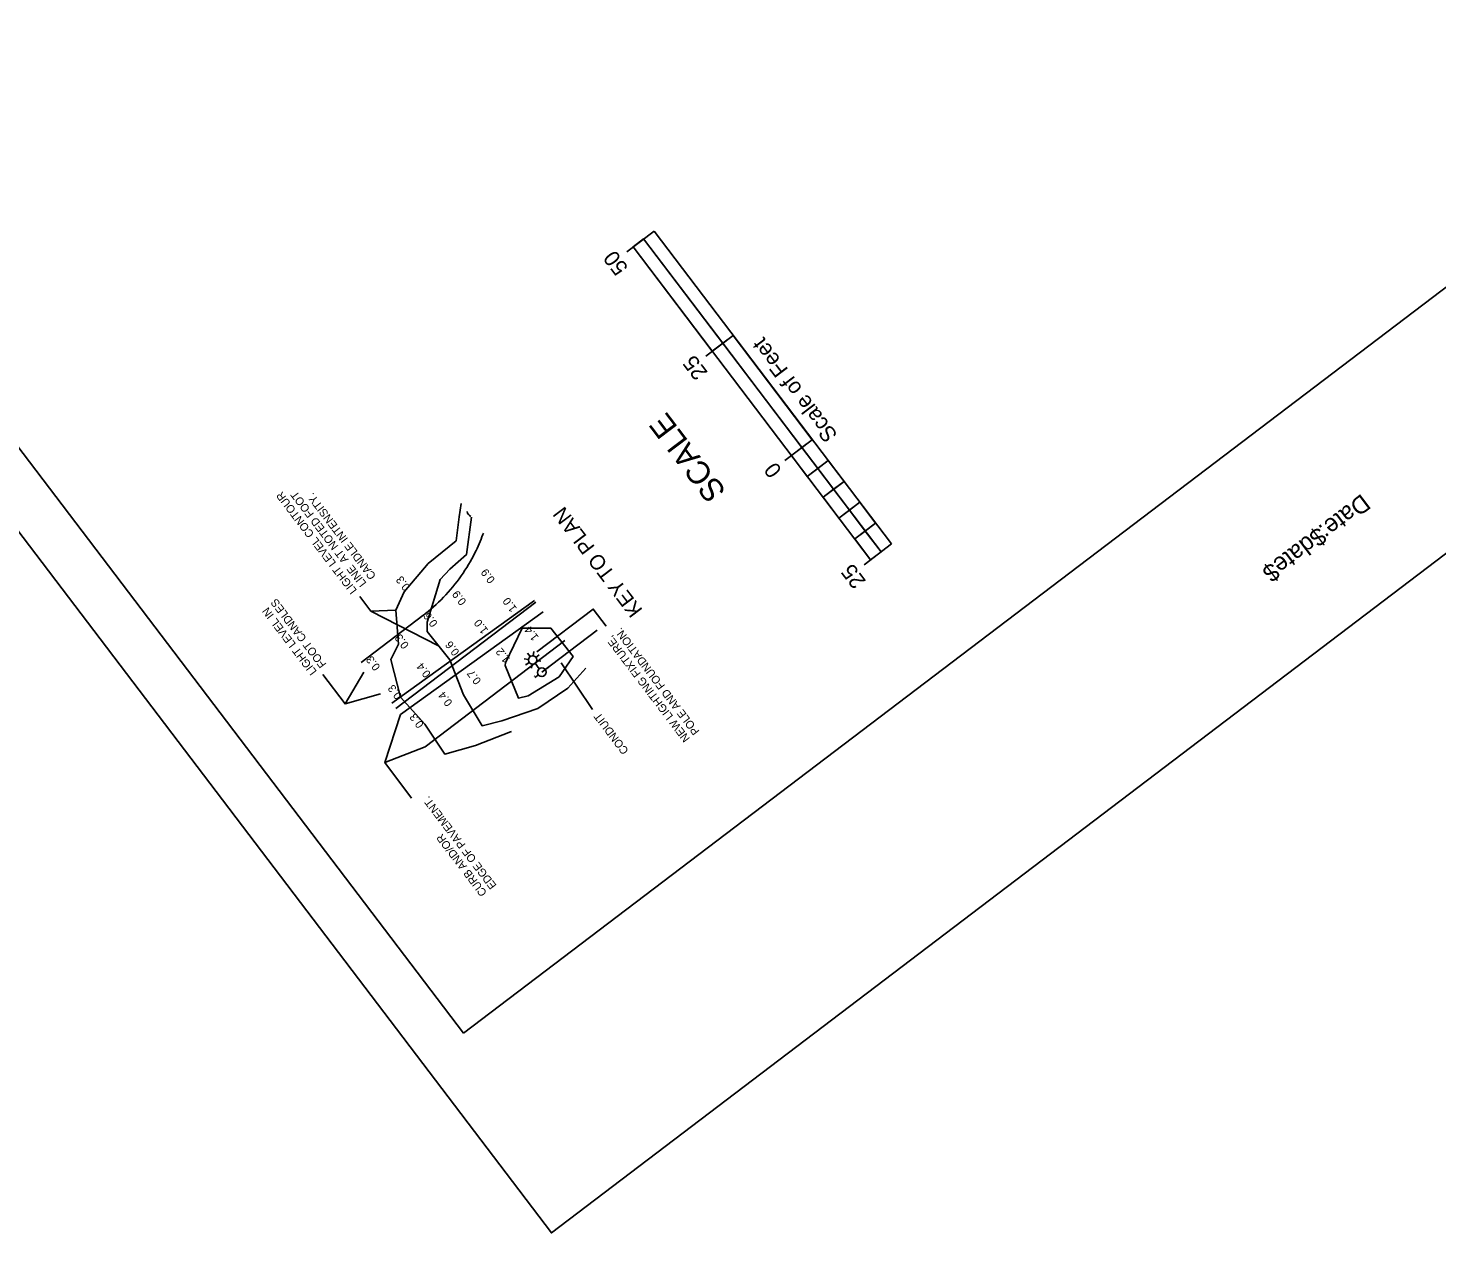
# Model space of a CAD drawing. Extents: x 1111477 to 1112429, y 616480 to 617490.
# Drawn here: x 1111891 to 1112159.9, y 616480.3 to 616710.3 of the extents above; entities that cross this region are included whole.
import ezdxf

# ---------------------------------------------------------------- set-up
doc = ezdxf.new("R2010")
doc.units = 0
for name, color, linetype in [('ANNOTATION', 7, 'Continuous'), ('D_Utilities_Pole_StreetLight', 7, 'Continuous'), ('H_V CONTROLS', 7, 'Continuous'), ('Liting Text', 7, 'Continuous'), ('VSL-LUMINAIRESCHEDULES', 7, 'Continuous'), ('VSL-STATISTICS', 7, 'Continuous')]:
    doc.layers.add(name, color=color, linetype=linetype)

msp = doc.modelspace()

# ---------------------------------------------------------------- linework, layer by layer
msp.add_lwpolyline([(1111990.86, 616480.3), (1111476.68, 617157.15), (1111914.64, 617489.85), (1112428.82, 616813)], close=True)
at = {"layer": 'ANNOTATION'}
for p, q in [((1111987.64, 616601.05), (1111960.41, 616581.46)), ((1111987.9, 616600.7), (1111961.2, 616580.42)), ((1111966.31, 616598.14), (1111954.55, 616589.2)), ((1111956.42, 616598.99), (1111969.32, 616592.41)), ((1111962.08, 616579.27), (1111989.31, 616598.85)), ((1111966.75, 616573.11), (1111993.45, 616593.39)), ((1111988.16, 616590.47), (1111988.13, 616590.5)), ((1111998.73, 616580.25), (1111992.75, 616589.16)), ((1111951.48, 616581.3), (1111955.05, 616587.36)), ((1111985.97, 616588.8), (1111985.94, 616588.84)), ((1111987.63, 616586.61), (1111987.6, 616586.65)), ((1111988.85, 616587), (1111988.85, 616587)), ((1111989.05, 616586.72), (1111989.05, 616586.72)), ((1111989.12, 616587.21), (1111989.12, 616587.21)), ((1111989.33, 616586.93), (1111989.33, 616586.93)), ((1111959.05, 616570.09), (1111966.75, 616573.11))]:
    msp.add_line(p, q, dxfattribs=at)
for points in [[(1111983.23, 616576.04), (1111983.05, 616575.95), (1111976.37, 616573.35), (1111970.51, 616571.7), (1111966.69, 616577.44), (1111962.05, 616582.57), (1111960.2, 616589.8), (1111961.7, 616592.71), (1111961.16, 616599.19), (1111962.78, 616602.68), (1111967.33, 616608.07), (1111972.66, 616612.43), (1111973.28, 616617.03), (1111973.62, 616619.54)], [(1111997.44, 616588.12), (1111993.98, 616584.3), (1111988.3, 616580.41), (1111981.43, 616578.08), (1111977.65, 616577.13), (1111974.06, 616583.04), (1111971.46, 616589.71), (1111967.18, 616595.11), (1111967.18, 616596.88), (1111969.61, 616605.07), (1111971.5, 616607.04), (1111974.65, 616609.81), (1111975.6, 616616.93)], [(1111954.3, 616601.79), (1111956.42, 616598.99), (1111961.16, 616599.19)], [(1112001.31, 616596.15), (1111998.85, 616599.39), (1111988.09, 616591.22)], [(1111995.03, 616590.33), (1111990.79, 616595.75), (1111985.29, 616595.78), (1111982.1, 616589.15), (1111982.07, 616588.63), (1111984.58, 616582.39), (1111986.45, 616582.86), (1111992.34, 616586.48), (1111995.03, 616590.33)], [(1111947.23, 616586.9), (1111951.48, 616581.3), (1111958.24, 616583.23)], [(1111964.19, 616563.31), (1111959.05, 616570.09), (1111962.08, 616579.27)]]:
    msp.add_lwpolyline(points, dxfattribs=at)
for centre, major_axis, start_param, end_param in [((1111976.12, 616618.3), (-0.05, 1.38), 1.737973, 2.633498), ((1111945.51, 616625.57), (-1.18, 34.42), 4.213502, 4.323837), ((1111945.51, 616625.57), (-1.18, 34.42), 4.323837, 4.333024), ((1111945.51, 616625.57), (-1.18, 34.42), 4.064294, 4.213502), ((1111945.51, 616625.57), (-1.18, 34.42), 3.756531, 4.064294)]:
    msp.add_ellipse(centre, major_axis=major_axis, ratio=0.998974, start_param=start_param, end_param=end_param, dxfattribs=at)
at = {"layer": 'D_Utilities_Pole_StreetLight'}
for p, q in [((1111986.49, 616589.79), (1111985.7, 616589.91)), ((1111986.65, 616589.2), (1111986.01, 616588.72)), ((1111986.8, 616590.32), (1111986.32, 616590.96)), ((1111987.17, 616588.89), (1111987.06, 616588.1)), ((1111987.4, 616590.47), (1111987.51, 616591.27)), ((1111988.56, 616587.99), (1111987.77, 616589.04)), ((1111987.92, 616590.16), (1111988.56, 616590.65)), ((1111988.08, 616589.57), (1111988.87, 616589.46)), ((1111988.39, 616586.85), (1111987.74, 616586.35)), ((1111989.7, 616587.83), (1111990.36, 616588.32))]:
    msp.add_line(p, q, dxfattribs=at)
for centre, major_axis in [((1111987.29, 616589.68), (0.027, -0.8)), ((1111989.05, 616587.34), (-0.028, 0.82))]:
    msp.add_ellipse(centre, major_axis=major_axis, ratio=0.998974, dxfattribs=at)
at = {"layer": 'H_V CONTROLS'}
for p, q in [((1112010.47, 616671.58), (1112005.24, 616667.61)), ((1112053.8, 616610.32), (1112008.48, 616670.07)), ((1112010.47, 616671.58), (1112055.79, 616611.83)), ((1112051.81, 616608.8), (1112006.48, 616668.56)), ((1112025.57, 616651.66), (1112020.35, 616647.7)), ((1112035.45, 616627.78), (1112040.68, 616631.74)), ((1112043.7, 616627.76), (1112039.72, 616624.74)), ((1112046.73, 616623.78), (1112042.74, 616620.75)), ((1112049.75, 616619.79), (1112045.76, 616616.77)), ((1112052.77, 616615.81), (1112048.79, 616612.79)), ((1112055.79, 616611.83), (1112050.56, 616607.86))]:
    msp.add_line(p, q, dxfattribs=at)
for points in [[(1112023.58, 616650.15), (1112008.48, 616670.07), (1112006.48, 616668.56), (1112021.59, 616648.64), (1112023.58, 616650.15)], [(1112023.58, 616650.15), (1112038.69, 616630.23), (1112040.68, 616631.74), (1112025.57, 616651.66), (1112023.58, 616650.15)], [(1112041.71, 616626.25), (1112038.69, 616630.23), (1112036.7, 616628.72), (1112039.72, 616624.74), (1112041.71, 616626.25)], [(1112044.73, 616622.27), (1112046.73, 616623.78), (1112043.7, 616627.76), (1112041.71, 616626.25), (1112044.73, 616622.27)], [(1112044.73, 616622.27), (1112042.74, 616620.75), (1112045.76, 616616.77), (1112047.76, 616618.28), (1112044.73, 616622.27)], [(1112050.78, 616614.3), (1112052.77, 616615.81), (1112049.75, 616619.79), (1112047.76, 616618.28), (1112050.78, 616614.3)], [(1112050.78, 616614.3), (1112048.79, 616612.79), (1112051.81, 616608.8), (1112053.8, 616610.32), (1112050.78, 616614.3)]]:
    msp.add_lwpolyline(points, dxfattribs=at)
at = {"layer": 'Liting Text'}
msp.add_line((1111989.05, 616587.34), (1111999.61, 616595.36), dxfattribs=at)
at = {"layer": 'VSL-LUMINAIRESCHEDULES'}
msp.add_lwpolyline([(1112428.82, 616813), (1111914.64, 617489.85), (1111476.68, 617157.15), (1111990.86, 616480.3)], close=True, dxfattribs=at)
at = {"layer": 'VSL-STATISTICS'}
for p, q in [((1111490.18, 617155.43), (1111974.11, 616518.4)), ((1111974.11, 616518.4), (1112392.16, 616835.98))]:
    msp.add_line(p, q, dxfattribs=at)

# ---------------------------------------------------------------- texts
at = {"layer": 'ANNOTATION'}
for s, height, p in [('LIGHT LEVEL CONTOUR', 1.528, (1111953.82, 616602.97)), ('LINE  AT NOTED FOOT', 1.528, (1111955.64, 616604.35)), ('CANDLE INTENSITY.', 1.528, (1111957.47, 616605.74)), ('KEY TO PLAN', 2.8603, (1112008.4, 616599.21)), ('0.3', 1.528, (1111964, 616603.6)), ('0.9', 1.528, (1111980.21, 616605.01)), ('0.9', 1.528, (1111974.73, 616600.84)), ('LIGHT LEVEL IN', 1.528, (1111946.16, 616587.48)), ('FOOT CANDLES', 1.528, (1111947.98, 616588.87)), ('1.0', 1.528, (1111984.37, 616599.52)), ('0.6', 1.528, (1111969.25, 616596.68)), ('1.0', 1.528, (1111978.89, 616595.36)), ('0.3', 1.528, (1111963.77, 616592.52)), ('1.4', 1.528, (1111988.53, 616594.03)), ('NEW LIGHTING FIXTURE,', 1.528, (1112017.41, 616574.69)), ('POLE AND FOUNDATION.', 1.528, (1112019.23, 616576.07)), ('0.6', 1.528, (1111973.41, 616591.19)), ('1.2', 1.528, (1111983.05, 616589.87)), ('0.3', 1.528, (1111958.29, 616588.35)), ('0.4', 1.528, (1111967.93, 616587.03)), ('0.7', 1.528, (1111977.57, 616585.71)), ('0.3', 1.528, (1111962.44, 616582.87)), ('0.4', 1.528, (1111972.08, 616581.54)), ('0.3', 1.528, (1111966.6, 616577.38)), ('CONDUIT', 1.528, (1112005.7, 616572.36)), ('EDGE OF PAVEMENT.', 1.528, (1111980.47, 616546.63)), ('CURB AND/OR', 1.528, (1111978.64, 616545.24))]:
    msp.add_text(s, height=height, rotation=127.1638, dxfattribs=at).set_placement(p)
at = {"layer": 'H_V CONTROLS'}
for s, height, p in [('50', 3, (1112005.66, 616664.57)), ('Scale of Feet', 3, (1112045.63, 616632.67)), ('25', 3, (1112020.83, 616644.58)), ('SCALE', 4.375, (1112024.37, 616621.91)), ('0', 3, (1112034.99, 616625.91)), ('25', 3, (1112051.04, 616604.75))]:
    msp.add_text(s, height=height, rotation=127.1806, dxfattribs=at).set_placement(p)
at = {"layer": 'VSL-STATISTICS'}
for s, p in [('Date:', (1112145.55, 616621.54)), ('$date$', (1112137.24, 616615.23))]:
    msp.add_text(s, height=3.348, rotation=217.2225, dxfattribs=at).set_placement(p)

doc.saveas('drawing.dxf')
